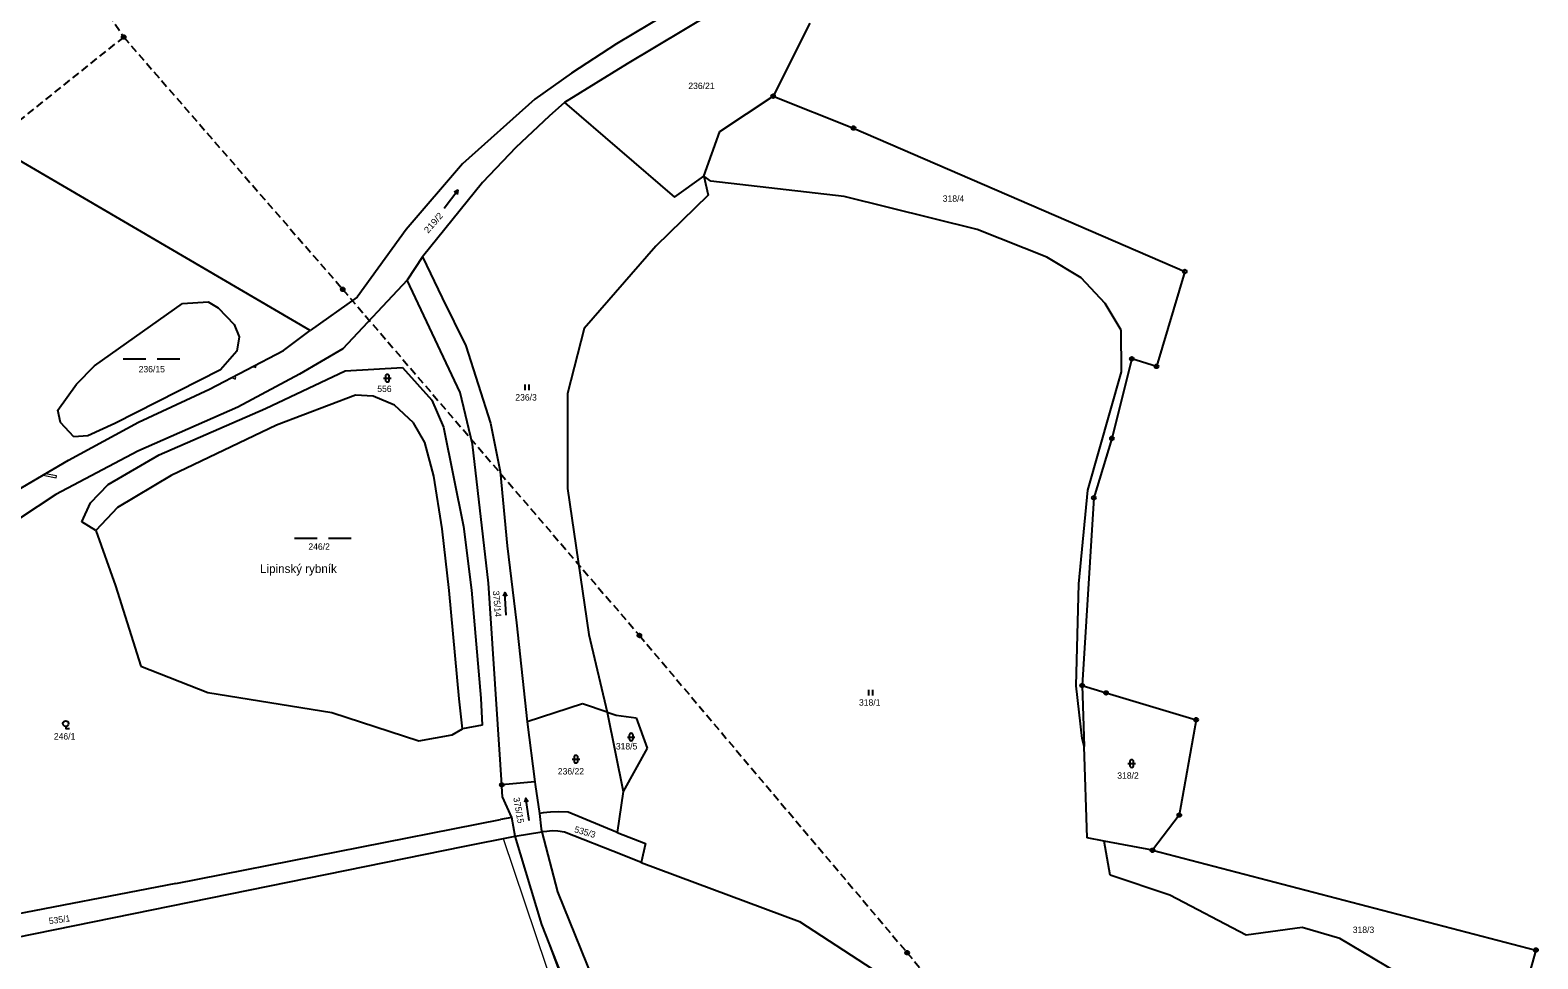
# Model space of a CAD drawing. Extents: x -885985 to -883535, y -1030025 to -1027941.
# Drawn here: x -884422.7 to -884023.3, y -1028576.6 to -1028330.5 of the extents above; entities that cross this region are included whole.
import ezdxf
from ezdxf.enums import TextEntityAlignment as Align

# ---------------------------------------------------------------- set-up
doc = ezdxf.new("R2010")
doc.units = 0
doc.header["$LTSCALE"] = 0.68
doc.linetypes.add('MEDIUM_DASHED', pattern=[4.5, 3, -1.5])
for name, color, linetype, lineweight in [('1', 7, 'Continuous', 25), ('13', 7, 'Continuous', 13), ('3', 7, 'Continuous', 25), ('6', 7, 'Continuous', 25), ('7', 7, 'Continuous', 13), ('8', 7, 'Continuous', 25)]:
    doc.layers.add(name, color=color, linetype=linetype, lineweight=lineweight)
doc.layers.add('2', color=7, linetype='Continuous')

msp = doc.modelspace()

# ---------------------------------------------------------------- linework, layer by layer
at = {"layer": '1'}
for p, q in [((-884245.65, -1028321.14), (-884267.33, -1028334.09)), ((-884241.93, -1028325.94), (-884264.57, -1028339.46)), ((-884216.17, -1028328.68), (-884225.88, -1028347.99)), ((-884267.33, -1028334.09), (-884279.26, -1028341.92)), ((-884264.57, -1028339.46), (-884281.12, -1028349.68)), ((-884279.26, -1028341.92), (-884289.01, -1028348.77)), ((-884289.01, -1028348.77), (-884308.12, -1028365.96)), ((-884239.95, -1028357.37), (-884225.88, -1028347.99)), ((-884225.88, -1028347.99), (-884204.58, -1028356.45)), ((-884281.12, -1028349.68), (-884285.2, -1028353.33)), ((-884281.12, -1028349.68), (-884251.97, -1028374.75)), ((-884285.2, -1028353.33), (-884294.05, -1028361.63)), ((-884204.58, -1028356.45), (-884116.82, -1028394.47)), ((-884244.23, -1028369.23), (-884239.95, -1028357.37)), ((-884348.51, -1028410.11), (-884432.41, -1028361.04)), ((-884294.05, -1028361.63), (-884302.88, -1028370.91)), ((-884308.12, -1028365.96), (-884323.09, -1028383.33)), ((-884302.88, -1028370.91), (-884318.76, -1028390.56)), ((-884251.97, -1028374.75), (-884244.23, -1028369.23)), ((-884242.34, -1028370.51), (-884244.23, -1028369.23)), ((-884244.23, -1028369.23), (-884243.1, -1028374.24)), ((-884207.05, -1028374.63), (-884242.34, -1028370.51)), ((-884243.1, -1028374.24), (-884256.96, -1028387.79)), ((-884171.83, -1028383.37), (-884207.05, -1028374.63)), ((-884323.09, -1028383.33), (-884336.09, -1028401.24)), ((-884153.35, -1028390.67), (-884171.83, -1028383.37)), ((-884256.96, -1028387.79), (-884275.91, -1028409.6)), ((-884318.76, -1028390.56), (-884322.84, -1028396.73)), ((-884318.76, -1028390.56), (-884313.58, -1028401.44)), ((-884144.27, -1028396.16), (-884153.35, -1028390.67)), ((-884322.84, -1028396.73), (-884339.82, -1028414.97)), ((-884308.75, -1028426.54), (-884322.84, -1028396.73)), ((-884137.89, -1028402.91), (-884144.27, -1028396.16)), ((-884116.82, -1028394.47), (-884124.31, -1028419.6)), ((-884405.66, -1028419.47), (-884382.35, -1028402.98)), ((-884382.35, -1028402.98), (-884375.48, -1028402.53)), ((-884375.48, -1028402.53), (-884372.87, -1028404.14)), ((-884372.87, -1028404.14), (-884368.66, -1028408.53)), ((-884336.09, -1028401.24), (-884348.51, -1028410.11)), ((-884313.58, -1028401.44), (-884307.31, -1028414.15)), ((-884133.66, -1028410.02), (-884137.89, -1028402.91)), ((-884368.66, -1028408.53), (-884367.35, -1028411.82)), ((-884367.35, -1028411.82), (-884367.9, -1028415.58)), ((-884355.57, -1028415.37), (-884348.51, -1028410.11)), ((-884275.91, -1028409.6), (-884280.33, -1028426.84)), ((-884133.61, -1028421.02), (-884133.66, -1028410.02)), ((-884375.21, -1028425.65), (-884355.57, -1028415.37)), ((-884367.9, -1028415.58), (-884372.24, -1028420.55)), ((-884339.82, -1028414.97), (-884351.29, -1028421.7)), ((-884307.31, -1028414.15), (-884300.72, -1028434.63)), ((-884410.37, -1028424.36), (-884405.66, -1028419.47)), ((-884372.24, -1028420.55), (-884400.21, -1028434.76)), ((-884360.34, -1028430.8), (-884339.2, -1028420.78)), ((-884339.2, -1028420.78), (-884324.04, -1028419.95)), ((-884324.04, -1028419.95), (-884316.3, -1028428.56)), ((-884130.88, -1028417.62), (-884136.14, -1028438.69)), ((-884124.31, -1028419.6), (-884130.88, -1028417.62)), ((-884415.33, -1028431.23), (-884410.37, -1028424.36)), ((-884351.29, -1028421.7), (-884367.63, -1028430.41)), ((-884142.49, -1028452.39), (-884133.61, -1028421.02)), ((-884394, -1028434.42), (-884375.21, -1028425.65)), ((-884336.47, -1028427.24), (-884357.42, -1028435.17)), ((-884331.85, -1028427.53), (-884336.47, -1028427.24)), ((-884326.19, -1028429.85), (-884331.85, -1028427.53)), ((-884316.3, -1028428.56), (-884313.15, -1028435.76)), ((-884305.51, -1028440.19), (-884308.75, -1028426.54)), ((-884280.33, -1028426.84), (-884280.33, -1028452.01)), ((-884414.65, -1028434.52), (-884415.33, -1028431.23)), ((-884367.63, -1028430.41), (-884394.11, -1028442.05)), ((-884388.54, -1028443.09), (-884360.34, -1028430.8)), ((-884321.14, -1028434.58), (-884326.19, -1028429.85)), ((-884411.11, -1028438.28), (-884414.65, -1028434.52)), ((-884412.49, -1028444.45), (-884394, -1028434.42)), ((-884400.21, -1028434.76), (-884407.42, -1028438.06)), ((-884357.42, -1028435.17), (-884385.33, -1028448.51)), ((-884318.1, -1028439.78), (-884321.14, -1028434.58)), ((-884313.15, -1028435.76), (-884307.93, -1028462.06)), ((-884300.72, -1028434.63), (-884298.2, -1028447.44)), ((-884407.42, -1028438.06), (-884411.11, -1028438.28)), ((-884315.79, -1028448.73), (-884318.1, -1028439.78)), ((-884301.24, -1028477.08), (-884305.51, -1028440.19)), ((-884136.14, -1028438.69), (-884140.93, -1028454.45)), ((-884430.24, -1028454.93), (-884412.49, -1028444.45)), ((-884394.11, -1028442.05), (-884415.83, -1028453.58)), ((-884401.97, -1028450.88), (-884388.54, -1028443.09)), ((-884385.33, -1028448.51), (-884399.58, -1028457.03)), ((-884313.58, -1028462.66), (-884315.79, -1028448.73)), ((-884298.2, -1028447.44), (-884296.29, -1028467.18)), ((-884406.68, -1028455.8), (-884401.97, -1028450.88)), ((-884280.33, -1028452.01), (-884274.73, -1028490.65)), ((-884144.93, -1028477.28), (-884142.49, -1028452.39)), ((-884415.83, -1028453.58), (-884425.5, -1028459.92)), ((-884408.97, -1028460.78), (-884406.68, -1028455.8)), ((-884140.93, -1028454.45), (-884144.01, -1028504.16)), ((-884399.58, -1028457.03), (-884405.25, -1028463.08)), ((-884405.25, -1028463.08), (-884408.97, -1028460.78)), ((-884405.25, -1028463.08), (-884400.05, -1028477.78)), ((-884311.66, -1028478.99), (-884313.58, -1028462.66)), ((-884307.93, -1028462.06), (-884305.74, -1028478.96)), ((-884296.29, -1028467.18), (-884293.88, -1028487.55)), ((-884400.05, -1028477.78), (-884393.35, -1028499.04)), ((-884309.06, -1028507.75), (-884311.66, -1028478.99)), ((-884305.74, -1028478.96), (-884303.28, -1028507.55)), ((-884297.74, -1028530.49), (-884301.24, -1028477.08)), ((-884145.59, -1028504.28), (-884144.93, -1028477.28)), ((-884293.88, -1028487.55), (-884291, -1028513.79)), ((-884274.73, -1028490.65), (-884269.8, -1028511.24)), ((-884393.35, -1028499.04), (-884375.57, -1028506.08)), ((-884143.98, -1028518.22), (-884145.59, -1028504.28)), ((-884144.01, -1028504.16), (-884143.49, -1028520.33)), ((-884144.01, -1028504.16), (-884137.69, -1028506.15)), ((-884375.57, -1028506.08), (-884342.8, -1028511.32)), ((-884308.11, -1028515.65), (-884309.06, -1028507.75)), ((-884303.28, -1028507.55), (-884302.95, -1028514.66)), ((-884137.69, -1028506.15), (-884113.83, -1028513.24)), ((-884342.8, -1028511.32), (-884319.71, -1028518.82)), ((-884276.4, -1028509.01), (-884291, -1028513.79)), ((-884269.8, -1028511.24), (-884276.4, -1028509.01)), ((-884269.8, -1028511.24), (-884267.41, -1028512.05)), ((-884269.8, -1028511.24), (-884265.57, -1028532.3)), ((-884267.41, -1028512.05), (-884262.14, -1028512.73)), ((-884310.91, -1028517.22), (-884308.11, -1028515.65)), ((-884302.95, -1028514.66), (-884308.11, -1028515.65)), ((-884291, -1028513.79), (-884288.96, -1028529.7)), ((-884262.14, -1028512.73), (-884259.21, -1028520.83)), ((-884113.83, -1028513.24), (-884118.29, -1028538.52)), ((-884319.71, -1028518.82), (-884310.91, -1028517.22)), ((-884143.49, -1028520.33), (-884143.98, -1028518.22)), ((-884142.71, -1028544.56), (-884143.49, -1028520.33)), ((-884259.21, -1028520.83), (-884265.57, -1028532.3)), ((-884288.96, -1028529.7), (-884297.74, -1028530.49)), ((-884297.74, -1028530.49), (-884297.71, -1028530.99)), ((-884297.6, -1028533.66), (-884297.71, -1028530.99)), ((-884288.96, -1028529.7), (-884288.93, -1028530.39)), ((-884288.93, -1028530.39), (-884287.78, -1028538.07)), ((-884265.57, -1028532.3), (-884267.16, -1028543.13)), ((-884295.09, -1028539.16), (-884297.6, -1028533.66)), ((-884384.12, -1028556.66), (-884298.05, -1028539.73)), ((-884295.09, -1028539.16), (-884298.05, -1028539.73)), ((-884294.23, -1028544.1), (-884295.09, -1028539.16)), ((-884286.79, -1028537.94), (-884287.78, -1028538.07)), ((-884287.78, -1028538.07), (-884287.31, -1028542.18)), ((-884284.8, -1028537.77), (-884286.79, -1028537.94)), ((-884282.8, -1028537.69), (-884284.8, -1028537.77)), ((-884280.18, -1028537.76), (-884282.8, -1028537.69)), ((-884267.16, -1028543.13), (-884280.18, -1028537.76)), ((-884118.29, -1028538.52), (-884125.39, -1028547.86)), ((-884308.01, -1028546.89), (-884294.23, -1028544.1)), ((-884294.23, -1028544.1), (-884287.1, -1028543)), ((-884287.11, -1028567.53), (-884294.23, -1028544.1)), ((-884287.31, -1028542.18), (-884287.1, -1028543)), ((-884285.78, -1028542.88), (-884287.1, -1028543)), ((-884287.1, -1028543), (-884283, -1028558.83)), ((-884284.37, -1028542.68), (-884285.78, -1028542.88)), ((-884282.87, -1028542.8), (-884284.37, -1028542.68)), ((-884281.14, -1028543.05), (-884282.87, -1028542.8)), ((-884265.82, -1028549.09), (-884281.14, -1028543.05)), ((-884267.16, -1028543.13), (-884259.68, -1028546.01)), ((-884138.19, -1028545.42), (-884142.71, -1028544.56)), ((-884434.95, -1028572.64), (-884308.01, -1028546.89)), ((-884259.68, -1028546.01), (-884260.81, -1028551.1)), ((-884136.56, -1028554.41), (-884138.19, -1028545.42)), ((-884125.39, -1028547.86), (-884138.19, -1028545.42)), ((-884125.39, -1028547.86), (-884023.81, -1028574.28)), ((-884260.81, -1028551.1), (-884265.82, -1028549.09)), ((-884260.81, -1028551.1), (-884218.86, -1028566.7)), ((-884120.78, -1028559.74), (-884136.56, -1028554.41)), ((-884384.12, -1028556.66), (-884436.23, -1028566.74)), ((-884283, -1028558.83), (-884264.4, -1028604.66)), ((-884100.6, -1028570.39), (-884120.78, -1028559.74)), ((-884278.86, -1028588.6), (-884287.11, -1028567.53)), ((-884218.86, -1028566.7), (-884169.49, -1028598.85)), ((-884085.72, -1028568.33), (-884100.6, -1028570.39)), ((-884075.72, -1028571.19), (-884085.72, -1028568.33)), ((-884036.49, -1028594.56), (-884075.72, -1028571.19)), ((-884023.81, -1028574.28), (-884033.74, -1028609.04))]:
    msp.add_line(p, q, dxfattribs=at)
at = {"layer": '13'}
for points in [[(-884363.11, -1028419.32), (-884363.8, -1028419.68), (-884362.93, -1028419.87), (-884362.85, -1028419.38)], [(-884368.71, -1028422.25), (-884369.26, -1028422.54), (-884368.37, -1028422.96), (-884368.18, -1028422.5)], [(-884418.59, -1028448.05), (-884419.24, -1028448.44), (-884415.79, -1028449.11), (-884415.72, -1028448.61)], [(-884297.74, -1028530.49), (-884297.71, -1028530.99), (-884297.6, -1028533.66), (-884295.09, -1028539.16), (-884294.23, -1028544.1), (-884287.1, -1028543), (-884287.31, -1028542.18), (-884287.78, -1028538.07), (-884288.93, -1028530.39), (-884288.96, -1028529.7)], [(-884285.99, -1028578.59), (-884283.56, -1028585.47), (-884279.71, -1028596.38), (-884274.01, -1028614.24), (-884271.34, -1028621.15), (-884260.78, -1028648.45), (-884258.52, -1028650.86), (-884256.47, -1028651.82), (-884254.4, -1028652.78), (-884255.82, -1028648.81), (-884256.72, -1028648.39), (-884258.09, -1028646.92), (-884258.19, -1028646.82), (-884268.53, -1028620.09), (-884271.18, -1028613.25), (-884276.87, -1028595.43), (-884280.82, -1028584.67), (-884287.11, -1028567.53), (-884294.23, -1028544.1), (-884297.41, -1028544.74)]]:
    msp.add_lwpolyline(points, close=True, dxfattribs=at)
at = {"layer": '3'}
for p, q in [((-884309.397, -1028372.936), (-884309.585, -1028374.018)), ((-884398.029, -1028417.61), (-884392.029, -1028417.61)), ((-884389.029, -1028417.61), (-884383.029, -1028417.61)), ((-884329.061, -1028422.751), (-884327.059, -1028422.751)), ((-884328.561, -1028422.251), (-884328.561, -1028423.252)), ((-884327.559, -1028423.252), (-884327.559, -1028422.251)), ((-884291.521, -1028425.9), (-884291.521, -1028424.4)), ((-884290.52, -1028425.9), (-884290.52, -1028424.4)), ((-884352.659, -1028465.11), (-884346.659, -1028465.11)), ((-884343.659, -1028465.11), (-884337.659, -1028465.11)), ((-884296.982, -1028479.53), (-884296.414, -1028480.469)), ((-884200.501, -1028506.83), (-884200.501, -1028505.33)), ((-884199.5, -1028506.83), (-884199.5, -1028505.33)), ((-884264.491, -1028517.831), (-884262.489, -1028517.831)), ((-884263.991, -1028517.331), (-884263.991, -1028518.332)), ((-884262.989, -1028518.332), (-884262.989, -1028517.331)), ((-884279.091, -1028523.691), (-884277.089, -1028523.691)), ((-884278.591, -1028523.191), (-884278.591, -1028524.192)), ((-884277.589, -1028524.192), (-884277.589, -1028523.191)), ((-884131.391, -1028524.371), (-884131.391, -1028525.372)), ((-884130.389, -1028525.372), (-884130.389, -1028524.371)), ((-884131.891, -1028524.871), (-884129.889, -1028524.871)), ((-884291.404, -1028534.049), (-884290.755, -1028534.935))]:
    msp.add_line(p, q, dxfattribs=at)
for points in [[(-884313.008, -1028377.727), (-884309.397, -1028372.936), (-884310.386, -1028373.414)], [(-884296.563, -1028485.515), (-884296.982, -1028479.53), (-884297.414, -1028480.539)], [(-884413.26, -1028515.042), (-884413.26, -1028515.54), (-884412.259, -1028515.54)], [(-884290.465, -1028539.975), (-884291.404, -1028534.049), (-884291.746, -1028535.092)]]:
    msp.add_lwpolyline(points, dxfattribs=at)
msp.add_circle((-884413.2593, -1028514.2909), 0.75, dxfattribs=at)
for centre, start, end in [((-884328.06, -1028422.2509), 0, 180), ((-884328.06, -1028423.2509), 180, 359.98789), ((-884263.49, -1028517.3309), 0, 180), ((-884263.49, -1028518.3309), 180, 359.98789), ((-884278.09, -1028523.1909), 0, 180), ((-884278.09, -1028524.1909), 180, 359.98789), ((-884130.89, -1028524.3709), 0, 180), ((-884130.89, -1028525.3709), 180, 359.98789)]:
    msp.add_arc(centre, 0.5, start, end, dxfattribs=at)
at = {"layer": '6', "linetype": 'MEDIUM_DASHED'}
for p, q in [((-884468.25, -1028223.54), (-884397.9, -1028332.33)), ((-884397.9, -1028332.33), (-884449.91, -1028373.93)), ((-884397.9, -1028332.33), (-884339.87, -1028399.2)), ((-884339.87, -1028399.2), (-884261.29, -1028490.92)), ((-884261.29, -1028490.92), (-884190.37, -1028575)), ((-884190.37, -1028575), (-884113.3, -1028665.71))]:
    msp.add_line(p, q, dxfattribs=at)
at = {"layer": '6'}
for centre, radius in [((-884397.9034, -1028332.3299), 0.5), ((-884397.9034, -1028332.3299), 0.4), ((-884397.9034, -1028332.3299), 0.3), ((-884397.9034, -1028332.3299), 0.2), ((-884397.9034, -1028332.3299), 0.1), ((-884339.8734, -1028399.1999), 0.5), ((-884339.8734, -1028399.1999), 0.4), ((-884339.8734, -1028399.1999), 0.3), ((-884339.8734, -1028399.1999), 0.2), ((-884339.8734, -1028399.1999), 0.1), ((-884261.2934, -1028490.9199), 0.5), ((-884261.2934, -1028490.9199), 0.4), ((-884261.2934, -1028490.9199), 0.3), ((-884261.2934, -1028490.9199), 0.2), ((-884261.2934, -1028490.9199), 0.1), ((-884190.3734, -1028574.9999), 0.5), ((-884190.3734, -1028574.9999), 0.4), ((-884190.3734, -1028574.9999), 0.3), ((-884190.3734, -1028574.9999), 0.2), ((-884190.3734, -1028574.9999), 0.1)]:
    msp.add_circle(centre, radius, dxfattribs=at)
at = {"layer": '8'}
for centre, radius in [((-884225.88, -1028347.9899), 0.5), ((-884225.88, -1028347.9899), 0.0303), ((-884204.58, -1028356.4499), 0.5), ((-884204.58, -1028356.4499), 0.0303), ((-884116.82, -1028394.4699), 0.5), ((-884116.82, -1028394.4699), 0.0303), ((-884130.88, -1028417.6199), 0.5), ((-884130.88, -1028417.6199), 0.0303), ((-884124.31, -1028419.5999), 0.5), ((-884124.31, -1028419.5999), 0.0303), ((-884136.14, -1028438.6899), 0.5), ((-884136.14, -1028438.6899), 0.0303), ((-884140.93, -1028454.4499), 0.5), ((-884140.93, -1028454.4499), 0.0303), ((-884144.01, -1028504.1599), 0.5), ((-884144.01, -1028504.1599), 0.0303), ((-884137.69, -1028506.1499), 0.5), ((-884137.69, -1028506.1499), 0.0303), ((-884113.83, -1028513.2399), 0.5), ((-884113.83, -1028513.2399), 0.0303), ((-884297.74, -1028530.4899), 0.5), ((-884297.74, -1028530.4899), 0.0303), ((-884118.29, -1028538.5199), 0.5), ((-884118.29, -1028538.5199), 0.0303), ((-884125.39, -1028547.8599), 0.5), ((-884125.39, -1028547.8599), 0.0303), ((-884023.81, -1028574.2799), 0.5), ((-884023.81, -1028574.2799), 0.0303)]:
    msp.add_circle(centre, radius, dxfattribs=at)

# ---------------------------------------------------------------- texts
at = {"layer": '2'}
for s, p in [('236/21', (-884248.33, -1028346.115)), ('318/4', (-884180.94, -1028375.995)), ('556', (-884330.73, -1028426.395)), ('236/3', (-884294.16, -1028428.665)), ('246/2', (-884348.98, -1028468.225)), ('318/1', (-884203.13, -1028509.525)), ('246/1', (-884416.39, -1028518.505)), ('318/5', (-884267.53, -1028521.135)), ('236/22', (-884282.91, -1028527.765)), ('318/2', (-884134.71, -1028528.895)), ('318/3', (-884072.34, -1028569.765))]:
    msp.add_text(s, height=1.7, dxfattribs=at).set_placement(p)
at = {"layer": '2', "width": 1.1}
msp.add_text('219/2', height=1.7, rotation=49, dxfattribs=at).set_placement((-884317.259, -1028384.468))
at = {"layer": '2'}
msp.add_text('236/15', height=1.7, dxfattribs=at).set_placement((-884390.46, -1028421.195), align=Align.CENTER)
for s, rotation, p in [('375/14', 275, (-884299.8296, -1028482.6139)), ('375/15', 280, (-884294.1048, -1028537.4089))]:
    msp.add_text(s, height=1.7, rotation=rotation, dxfattribs=at).set_placement(p, align=Align.CENTER)
for s, rotation, p in [('535/3', 344, (-884278.667, -1028543.038)), ('535/1', 8, (-884417.6, -1028567.46))]:
    msp.add_text(s, height=1.7, rotation=rotation, dxfattribs=at).set_placement(p)
at = {"layer": '7'}
msp.add_text('Lipinský rybník', height=2.3, dxfattribs=at).set_placement((-884351.609, -1028474.365), align=Align.CENTER)

doc.saveas('drawing.dxf')
